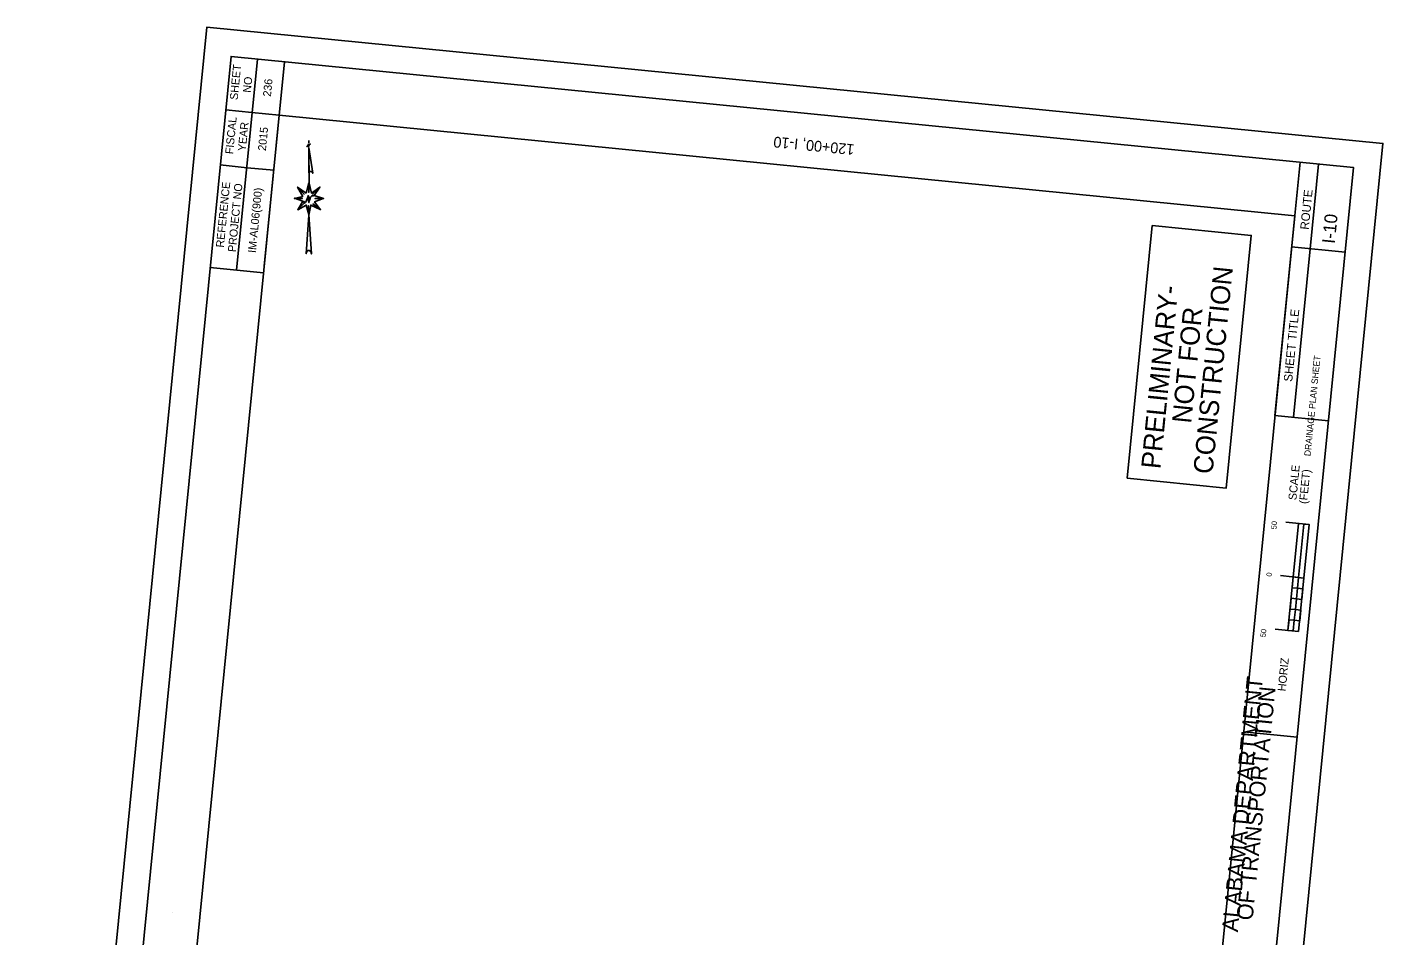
# Model space of a CAD drawing. Extents: x 1796928 to 1798191, y 245238 to 247038.
# Drawn here: x 1796928 to 1798191, y 246192 to 247038 of the extents above; entities that cross this region are included whole.
import ezdxf

# ---------------------------------------------------------------- set-up
doc = ezdxf.new("R2010")
doc.units = 0
for name, color, linetype in [('1', 7, 'Continuous'), ('ANNO-SHT', 7, 'Continuous'), ('ANNO-SYMB', 7, 'Continuous'), ('ANNO-TXT', 7, 'Continuous'), ('DRAINAGE', 7, 'Continuous'), ('Level 1', 7, 'Continuous'), ('Level 57', 7, 'Continuous'), ('Level 6', 7, 'Continuous'), ('Level 62', 7, 'Continuous'), ('SHT-BDR', 7, 'Continuous'), ('SHT-BNDRY', 7, 'Continuous')]:
    doc.layers.add(name, color=color, linetype=linetype)

# ---------------------------------------------------------------- blocks, each defined once
blk = doc.blocks.new('SC47208')
at = {"layer": 'Level 1'}
blk.add_line((0, 0), (0, 0), dxfattribs=at)

msp = doc.modelspace()

# ---------------------------------------------------------------- linework, layer by layer
at = {"layer": '1'}
msp.add_lwpolyline([(1797952.6, 246617.7), (1797975.9, 246852.9), (1798068, 246843.8), (1798044.8, 246608.6)], close=True, dxfattribs=at)
at = {"layer": 'ANNO-SYMB'}
for p, q in [((1798122, 246574.6), (1798100.1, 246576.8)), ((1798112, 246575.6), (1798102.2, 246476.1)), ((1798122, 246574.6), (1798112.1, 246475.1)), ((1798122, 246574.6), (1798117, 246575.1)), ((1798122, 246574.6), (1798117, 246575.1)), ((1798122, 246574.6), (1798117, 246575.1)), ((1798117, 246524.9), (1798095.2, 246527.1)), ((1798117, 246524.9), (1798095.2, 246527.1)), ((1798117, 246524.9), (1798095.2, 246527.1)), ((1798112.1, 246525.4), (1798107.1, 246525.9)), ((1798112.1, 246525.4), (1798107.1, 246525.9)), ((1798112.1, 246525.4), (1798107.1, 246525.9)), ((1798112.1, 246525.4), (1798110.1, 246505.5)), ((1798108.1, 246485.6), (1798103.2, 246486.1)), ((1798108.1, 246485.6), (1798103.2, 246486.1)), ((1798112.1, 246475.1), (1798090.2, 246477.3))]:
    msp.add_line(p, q, dxfattribs=at)
for points in [[(1798112.1, 246525.4), (1798117, 246575.1), (1798122, 246574.6), (1798117, 246524.9)], [(1798106.1, 246515.9), (1798107.1, 246525.9), (1798112.1, 246525.4), (1798111.1, 246515.4)], [(1798104.1, 246496), (1798105.1, 246506), (1798110.1, 246505.5), (1798109.1, 246495.5)], [(1798110.1, 246505.5), (1798111.1, 246515.4), (1798116.1, 246514.9), (1798115.1, 246505)], [(1798108.1, 246485.6), (1798109.1, 246495.5), (1798114.1, 246495), (1798113.1, 246485.1)], [(1798102.2, 246476.1), (1798103.2, 246486.1), (1798108.1, 246485.6), (1798107.1, 246475.6)]]:
    msp.add_lwpolyline(points, close=True, dxfattribs=at)
at = {"layer": 'ANNO-TXT'}
for p, q in [((1798122.9, 246831.4), (1798130.7, 246910.1)), ((1798107.4, 246674.5), (1798122.9, 246831.4))]:
    msp.add_line(p, q, dxfattribs=at)
at = {"layer": 'Level 57'}
msp.add_line((1797190.8, 246932.2), (1797190.7, 246929.8), dxfattribs=at)
for points in [[(1797191.9, 246928.7), (1797191.8, 246928.6), (1797191.9, 246928.5), (1797192, 246928.6), (1797192, 246928.8), (1797191.7, 246928.8), (1797191.5, 246928.7), (1797191.3, 246928.5), (1797191.1, 246928.2), (1797191, 246927.8), (1797190.8, 246927.2), (1797190.7, 246927), (1797190.6, 246926.6), (1797190.6, 246927.2), (1797190.6, 246928.2), (1797190.4, 246928.8), (1797190.4, 246928.2), (1797190.6, 246926.6), (1797190.6, 246928.2), (1797190.4, 246928.8), (1797190.2, 246928.2), (1797189.9, 246927.2), (1797189.6, 246926.6), (1797189.3, 246926.6), (1797189.1, 246926.6), (1797189, 246926.6), (1797189, 246926.8), (1797189.1, 246926.9), (1797189.2, 246926.9), (1797189.1, 246926.7)], [(1797190.7, 246925.7), (1797194.4, 246901.6), (1797194.2, 246902.3), (1797194, 246902.6), (1797193.6, 246903), (1797193.1, 246903.2), (1797192.8, 246903.3), (1797192.4, 246903.3), (1797192, 246903.3), (1797191.8, 246903.2), (1797191.4, 246903), (1797191.1, 246902.8), (1797190.9, 246902.5), (1797190.8, 246902.2), (1797190.7, 246902.1), (1797190.7, 246925.5), (1797190.9, 246892.6)], [(1797190.8, 246892.6), (1797190.6, 246883.7), (1797190.8, 246892.7), (1797188.1, 246883.1), (1797180.2, 246888.7), (1797186.3, 246882), (1797180.2, 246888.7), (1797185.1, 246880.1), (1797177.1, 246878.2), (1797184.8, 246878), (1797177.3, 246878.3), (1797185, 246875.5), (1797180.4, 246867.7), (1797186.2, 246873.4), (1797180.4, 246867.7), (1797188.3, 246872), (1797190.6, 246863.1), (1797190.5, 246871.5), (1797190.6, 246862.9), (1797192.6, 246871.9), (1797201.6, 246867.8), (1797192.5, 246871.9), (1797190.6, 246862.7), (1797188.3, 246826.7), (1797188.5, 246827.8), (1797188.8, 246828.6), (1797189.3, 246829.1), (1797189.9, 246829.6), (1797190.4, 246829.7), (1797191.1, 246829.7), (1797191.6, 246829.5), (1797192.1, 246829.2), (1797192.5, 246828.7), (1797192.9, 246828), (1797193, 246827.5), (1797193.2, 246826.6), (1797190.7, 246863.2), (1797192.5, 246872), (1797201.4, 246867.8), (1797194.6, 246873.1), (1797201.3, 246868), (1797196.1, 246875), (1797204.1, 246878.1), (1797196.5, 246878), (1797204.4, 246878.1), (1797195.6, 246880.8), (1797201.1, 246888.7), (1797194.6, 246882.3), (1797201.1, 246888.7), (1797193.1, 246883.1), (1797190.9, 246892.5)], [(1797194.6, 246880.6), (1797194.4, 246880.4), (1797194.7, 246880.2), (1797194.9, 246880.5), (1797194.8, 246880.9), (1797194.7, 246881), (1797194, 246880.9), (1797193.4, 246880.7), (1797192.4, 246879.4), (1797192.3, 246879), (1797191.9, 246877.8), (1797191.5, 246876.5), (1797191, 246875.7), (1797190.8, 246874.3), (1797190.8, 246876), (1797190.6, 246878.3), (1797190.5, 246879.5), (1797190, 246880.9), (1797190, 246879.2), (1797190.3, 246876.9), (1797190.5, 246875.5), (1797190.8, 246874.3), (1797190.8, 246876.4), (1797190.6, 246879.5), (1797190, 246880.9), (1797189.7, 246879.4), (1797189.1, 246877.8), (1797188.8, 246877.2), (1797188.5, 246876.3), (1797188.1, 246875.6), (1797187.8, 246875.1), (1797187.6, 246874.5), (1797186.8, 246874.1), (1797186.1, 246874.3), (1797185.9, 246874.5), (1797185.8, 246875.2), (1797186.2, 246875.5), (1797186.5, 246875.2), (1797186.3, 246874.9)]]:
    msp.add_lwpolyline(points, dxfattribs=at)
at = {"layer": 'Level 6'}
for p, q in [((1797142.9, 247007.8), (1797123.5, 246811.5)), ((1797168, 247005.4), (1797149.2, 246815)), ((1797137.6, 246958.1), (1797113.4, 246960.5)), ((1797137.6, 246958.1), (1797163.1, 246955.6)), ((1797133.2, 246906.8), (1797108.3, 246909.3)), ((1798113.4, 246911.8), (1798090.1, 246676.3)), ((1797133.2, 246906.8), (1797158, 246904.4)), ((1797098.9, 246813.9), (1797148.6, 246809))]:
    msp.add_line(p, q, dxfattribs=at)
at = {"layer": 'Level 62'}
msp.add_lwpolyline([(1798023.1, 245237.6), (1798190.5, 246929.3), (1797095.9, 247037.6), (1796928.5, 245345.9)], close=True, dxfattribs=at)
at = {"layer": 'SHT-BDR'}
msp.add_lwpolyline([(1797960.8, 245369.3), (1798108.5, 246862), (1797163.1, 246955.6), (1797015.4, 245462.9)], close=True, dxfattribs=at)
at = {"layer": 'SHT-BNDRY'}
for p, q in [((1798155.4, 246828.2), (1798105.6, 246833.1)), ((1798139.9, 246671.3), (1798090.1, 246676.3)), ((1798110.8, 246376.8), (1798060.9, 246381.7))]:
    msp.add_line(p, q, dxfattribs=at)
msp.add_lwpolyline([(1798004.4, 245302.2), (1798163.2, 246906.9), (1797118.3, 247010.3), (1796959.5, 245405.6)], close=True, dxfattribs=at)

# ---------------------------------------------------------------- block references
at = {"layer": 'DRAINAGE', "xscale": 1.0000020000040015, "yscale": 1.0000020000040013, "rotation": -32.067534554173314}
msp.add_blockref('SC47208', (1797063.6, 246213.4), dxfattribs=at)
msp.add_blockref('SC47208', (1797063.6, 246213.4), dxfattribs=at)

# ---------------------------------------------------------------- texts
at = {"layer": '1'}
for s, p in [('CONSTRUCTION', (1798031.9, 246621.1)), ('PRELIMINARY-', (1797983.4, 246625.9)), ('NOT FOR', (1798012.1, 246668.3))]:
    msp.add_text(s, height=18, rotation=84.3491, dxfattribs=at).set_placement(p)
at = {"layer": 'ANNO-SHT'}
for s, height, rotation, p in [('236', 7.45, 84.3491, (1797155.4, 246972.6)), ('2015', 7.45, 84.3491, (1797150.7, 246922.2)), ('120+00, I-10', 10, 174.3491, (1797698.9, 246928.4)), ('IM-AL06(900)', 7.449, 84.3491, (1797141.4, 246827.2)), ('  I-10  ', 12, 84.3491, (1798144.9, 246826.8)), ('               DRAINAGE PLAN SHEET               ', 6, 84.3491, (1798119.9, 246604.8))]:
    msp.add_text(s, height=height, rotation=rotation, dxfattribs=at).set_placement(p)
at = {"layer": 'ANNO-SYMB'}
for s, height, p in [('SCALE', 7.5, (1798110, 246597.1)), ('(FEET)', 7.5, (1798119.9, 246593.6)), (' 50', 5, (1798091.2, 246568.1)), ('0', 5, (1798087, 246526)), ('0', 5, (1798087, 246526)), ('0', 5, (1798087, 246526)), (' 50', 5, (1798081.2, 246467.7)), ('HORIZ', 7.5, (1798100, 246419.2))]:
    msp.add_text(s, height=height, rotation=84.4063, dxfattribs=at).set_placement(p)
at = {"layer": 'ANNO-TXT'}
for s, height, p in [('ROUTE', 8, (1798121.5, 246848.8)), ('SHEET TITLE', 8, (1798106.1, 246707.3)), ('ALABAMA DEPARTMENT', 15, (1798055.5, 246195)), ('OF TRANSPORTATION', 15, (1798069.2, 246205.8))]:
    msp.add_text(s, height=height, rotation=84.3491, dxfattribs=at).set_placement(p)
at = {"layer": 'Level 6'}
for s, p in [('SHEET', (1797124.5, 246969.6)), ('NO', (1797136.7, 246976.3)), ('FISCAL', (1797120.2, 246919.1)), ('YEAR', (1797132, 246921.9)), ('REFERENCE', (1797111.6, 246832.2)), ('PROJECT NO', (1797122.7, 246828))]:
    msp.add_text(s, height=7.44, rotation=84.3491, dxfattribs=at).set_placement(p)

doc.saveas('drawing.dxf')
